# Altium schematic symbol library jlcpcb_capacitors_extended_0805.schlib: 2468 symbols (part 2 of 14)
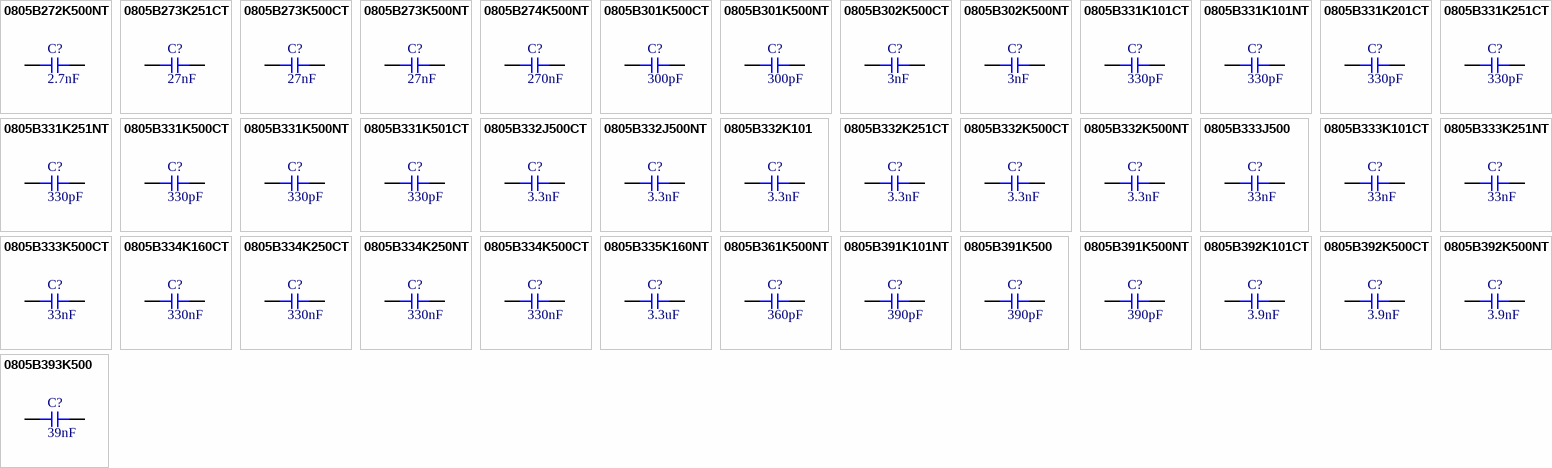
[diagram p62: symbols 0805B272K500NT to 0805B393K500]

## 0805B332K251CT
designator C?  Capacitance: 3.3nF  (hidden comment: *)
Capacitor, Ceramic (MLCC), 3.3nF, ±10%, 250V, X7R, ±10%, SMD 0805; Manufacturer: Walsin Tech Corp; Manufacturer Part Number: 0805B332K251CT
footprint CAP-0805 (0805 (2012M) Capacitor)
pins: 1, 2

## 0805B332K500CT
designator C?  Capacitance: 3.3nF  (hidden comment: *)
Capacitor, Ceramic (MLCC), 3.3nF, ±10%, 50V, X7R, ±10%, SMD 0805; Manufacturer: Walsin Tech Corp; Manufacturer Part Number: 0805B332K500CT
footprint CAP-0805 (0805 (2012M) Capacitor)
pins: 1, 2

## 0805B332K500NT
designator C?  Capacitance: 3.3nF  (hidden comment: *)
Capacitor, Ceramic (MLCC), 3.3nF, ±10%, 50V, X7R, ±10%, SMD 0805; Manufacturer: FH(Guangdong Fenghua Advanced Tech); Manufacturer Part Number: 0805B332K500NT
footprint CAP-0805 (0805 (2012M) Capacitor)
pins: 1, 2

## 0805B333J500
designator C?  Capacitance: 33nF  (hidden comment: *)
Capacitor, Ceramic (MLCC), 33nF, ±5%, 50V, X7R, ±5%, SMD 0805; Manufacturer: Walsin Tech Corp; Manufacturer Part Number: 0805B333J500
footprint CAP-0805 (0805 (2012M) Capacitor)
pins: 1, 2

## 0805B333K101CT
designator C?  Capacitance: 33nF  (hidden comment: *)
Capacitor, Ceramic (MLCC), 33nF, ±10%, 100V, X7R, ±10%, SMD 0805; Manufacturer: Walsin Tech Corp; Manufacturer Part Number: 0805B333K101CT
footprint CAP-0805 (0805 (2012M) Capacitor)
pins: 1, 2

## 0805B333K251NT
designator C?  Capacitance: 33nF  (hidden comment: *)
Capacitor, Ceramic (MLCC), 33nF, ±10%, 250V, ±10%, SMD 0805; Manufacturer: FH(Guangdong Fenghua Advanced Tech); Manufacturer Part Number: 0805B333K251NT
footprint CAP-0805 (0805 (2012M) Capacitor)
pins: 1, 2

## 0805B333K500CT
designator C?  Capacitance: 33nF  (hidden comment: *)
Capacitor, Ceramic (MLCC), 33nF, ±10%, 50V, X7R, ±10%, SMD 0805; Manufacturer: Walsin Tech Corp; Manufacturer Part Number: 0805B333K500CT
footprint CAP-0805 (0805 (2012M) Capacitor)
pins: 1, 2

## 0805B334K160CT
designator C?  Capacitance: 330nF  (hidden comment: *)
Capacitor, Ceramic (MLCC), 330nF, ±10%, 16V, X7R, ±10%, SMD 0805; Manufacturer: Walsin Tech Corp; Manufacturer Part Number: 0805B334K160CT
footprint CAP-0805 (0805 (2012M) Capacitor)
pins: 1, 2

## 0805B334K250CT
designator C?  Capacitance: 330nF  (hidden comment: *)
Capacitor, Ceramic (MLCC), 330nF, ±10%, 25V, X7R, ±10%, SMD 0805; Manufacturer: Walsin Tech Corp; Manufacturer Part Number: 0805B334K250CT
footprint CAP-0805 (0805 (2012M) Capacitor)
pins: 1, 2

## 0805B334K250NT
designator C?  Capacitance: 330nF  (hidden comment: *)
Capacitor, Ceramic (MLCC), 330nF, ±10%, 25V, X7R, ±10%, SMD 0805; Manufacturer: FH(Guangdong Fenghua Advanced Tech); Manufacturer Part Number: 0805B334K250NT
footprint CAP-0805 (0805 (2012M) Capacitor)
pins: 1, 2

## 0805B334K500CT
designator C?  Capacitance: 330nF  (hidden comment: *)
Capacitor, Ceramic (MLCC), 330nF, ±10%, 50V, X7R, ±10%, SMD 0805; Manufacturer: Walsin Tech Corp; Manufacturer Part Number: 0805B334K500CT
footprint CAP-0805 (0805 (2012M) Capacitor)
pins: 1, 2

## 0805B335K160NT
designator C?  Capacitance: 3.3uF  (hidden comment: *)
Capacitor, Ceramic (MLCC), 3.3uF, ±10%, 16V, X7R, ±10%, SMD 0805; Manufacturer: FH(Guangdong Fenghua Advanced Tech); Manufacturer Part Number: 0805B335K160NT
footprint CAP-0805 (0805 (2012M) Capacitor)
pins: 1, 2

## 0805B361K500NT
designator C?  Capacitance: 360pF  (hidden comment: *)
Capacitor, Ceramic (MLCC), 360pF, ±10%, 50V, X7R, ±10%, SMD 0805; Manufacturer: FH(Guangdong Fenghua Advanced Tech); Manufacturer Part Number: 0805B361K500NT
footprint CAP-0805 (0805 (2012M) Capacitor)
pins: 1, 2

## 0805B391K101NT
designator C?  Capacitance: 390pF  (hidden comment: *)
Capacitor, Ceramic (MLCC), 390pF, ±10%, 100V, X7R, ±10%, SMD 0805; Manufacturer: FH(Guangdong Fenghua Advanced Tech); Manufacturer Part Number: 0805B391K101NT
footprint CAP-0805 (0805 (2012M) Capacitor)
pins: 1, 2

## 0805B391K500
designator C?  Capacitance: 390pF  (hidden comment: *)
Capacitor, Ceramic (MLCC), 390pF, ±10%, 50V, X7R, ±10%, SMD 0805; Manufacturer: Walsin Tech Corp; Manufacturer Part Number: 0805B391K500
footprint CAP-0805 (0805 (2012M) Capacitor)
pins: 1, 2

## 0805B391K500NT
designator C?  Capacitance: 390pF  (hidden comment: *)
Capacitor, Ceramic (MLCC), 390pF, ±10%, 50V, X7R, ±10%, SMD 0805; Manufacturer: FH(Guangdong Fenghua Advanced Tech); Manufacturer Part Number: 0805B391K500NT
footprint CAP-0805 (0805 (2012M) Capacitor)
pins: 1, 2

## 0805B392K101CT
designator C?  Capacitance: 3.9nF  (hidden comment: *)
Capacitor, Ceramic (MLCC), 3.9nF, ±10%, 100V, X7R, ±10%, SMD 0805; Manufacturer: Walsin Tech Corp; Manufacturer Part Number: 0805B392K101CT
footprint CAP-0805 (0805 (2012M) Capacitor)
pins: 1, 2

## 0805B392K500CT
designator C?  Capacitance: 3.9nF  (hidden comment: *)
Capacitor, Ceramic (MLCC), 3.9nF, ±10%, 50V, X7R, ±10%, SMD 0805; Manufacturer: Walsin Tech Corp; Manufacturer Part Number: 0805B392K500CT
footprint CAP-0805 (0805 (2012M) Capacitor)
pins: 1, 2

## 0805B392K500NT
designator C?  Capacitance: 3.9nF  (hidden comment: *)
Capacitor, Ceramic (MLCC), 3.9nF, ±10%, 50V, X7R, ±10%, SMD 0805; Manufacturer: FH(Guangdong Fenghua Advanced Tech); Manufacturer Part Number: 0805B392K500NT
footprint CAP-0805 (0805 (2012M) Capacitor)
pins: 1, 2

## 0805B393K500
designator C?  Capacitance: 39nF  (hidden comment: *)
Capacitor, Ceramic (MLCC), 39nF, ±10%, 50V, X7R, ±10%, SMD 0805; Manufacturer: Walsin Tech Corp; Manufacturer Part Number: 0805B393K500
footprint CAP-0805 (0805 (2012M) Capacitor)
pins: 1, 2

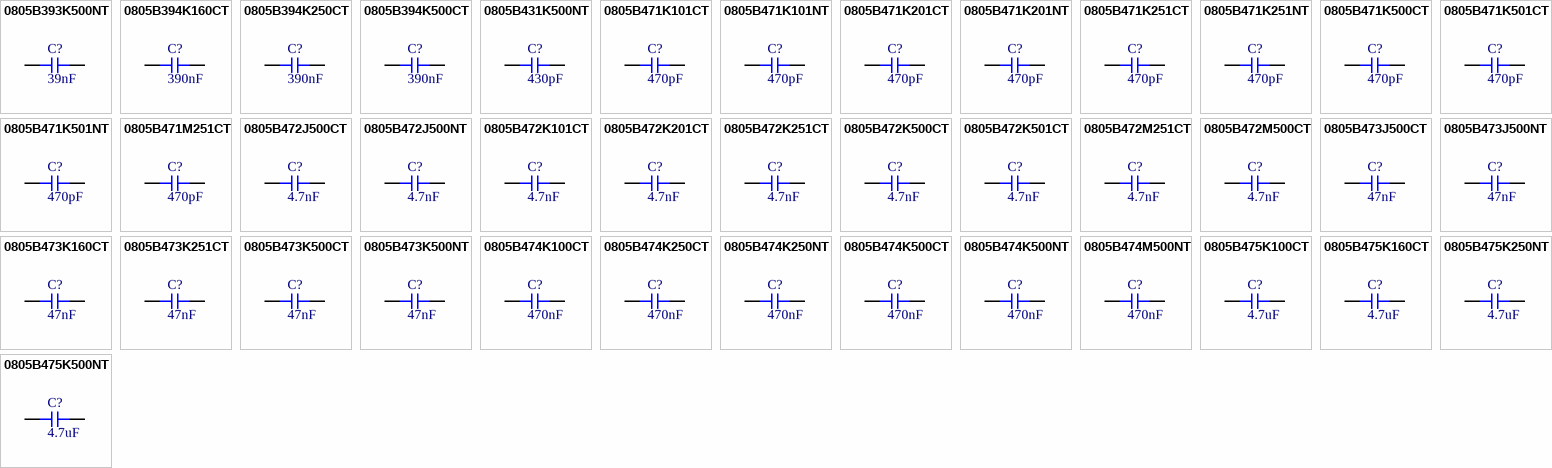
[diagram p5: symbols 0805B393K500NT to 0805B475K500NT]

## 0805B393K500NT
designator C?  Capacitance: 39nF  (hidden comment: *)
Capacitor, Ceramic (MLCC), 39nF, ±10%, 50V, X7R, ±10%, SMD 0805; Manufacturer: FH(Guangdong Fenghua Advanced Tech); Manufacturer Part Number: 0805B393K500NT
footprint CAP-0805 (0805 (2012M) Capacitor)
pins: 1, 2

## 0805B394K160CT
designator C?  Capacitance: 390nF  (hidden comment: *)
Capacitor, Ceramic (MLCC), 390nF, ±10%, 16V, X7R, ±10%, SMD 0805; Manufacturer: Walsin Tech Corp; Manufacturer Part Number: 0805B394K160CT
footprint CAP-0805 (0805 (2012M) Capacitor)
pins: 1, 2

## 0805B394K250CT
designator C?  Capacitance: 390nF  (hidden comment: *)
Capacitor, Ceramic (MLCC), 390nF, ±10%, 25V, X7R, ±10%, SMD 0805; Manufacturer: Walsin Tech Corp; Manufacturer Part Number: 0805B394K250CT
footprint CAP-0805 (0805 (2012M) Capacitor)
pins: 1, 2

## 0805B394K500CT
designator C?  Capacitance: 390nF  (hidden comment: *)
Capacitor, Ceramic (MLCC), 390nF, ±10%, 50V, X7R, ±10%, SMD 0805; Manufacturer: Walsin Tech Corp; Manufacturer Part Number: 0805B394K500CT
footprint CAP-0805 (0805 (2012M) Capacitor)
pins: 1, 2

## 0805B431K500NT
designator C?  Capacitance: 430pF  (hidden comment: *)
Capacitor, Ceramic (MLCC), 430pF, ±10%, 50V, X7R, ±10%, SMD 0805; Manufacturer: FH(Guangdong Fenghua Advanced Tech); Manufacturer Part Number: 0805B431K500NT
footprint CAP-0805 (0805 (2012M) Capacitor)
pins: 1, 2

## 0805B471K101CT
designator C?  Capacitance: 470pF  (hidden comment: *)
Capacitor, Ceramic (MLCC), 470pF, ±10%, 100V, X7R, ±10%, SMD 0805; Manufacturer: Walsin Tech Corp; Manufacturer Part Number: 0805B471K101CT
footprint CAP-0805 (0805 (2012M) Capacitor)
pins: 1, 2

## 0805B471K101NT
designator C?  Capacitance: 470pF  (hidden comment: *)
Capacitor, Ceramic (MLCC), 470pF, ±10%, 100V, X7R, ±10%, SMD 0805; Manufacturer: FH(Guangdong Fenghua Advanced Tech); Manufacturer Part Number: 0805B471K101NT
footprint CAP-0805 (0805 (2012M) Capacitor)
pins: 1, 2

## 0805B471K201CT
designator C?  Capacitance: 470pF  (hidden comment: *)
Capacitor, Ceramic (MLCC), 470pF, ±10%, 200V, X7R, ±10%, SMD 0805; Manufacturer: Walsin Tech Corp; Manufacturer Part Number: 0805B471K201CT
footprint CAP-0805 (0805 (2012M) Capacitor)
pins: 1, 2

## 0805B471K201NT
designator C?  Capacitance: 470pF  (hidden comment: *)
Capacitor, Ceramic (MLCC), 470pF, ±10%, 200V, X7R, ±10%, SMD 0805; Manufacturer: FH(Guangdong Fenghua Advanced Tech); Manufacturer Part Number: 0805B471K201NT
footprint CAP-0805 (0805 (2012M) Capacitor)
pins: 1, 2

## 0805B471K251CT
designator C?  Capacitance: 470pF  (hidden comment: *)
Capacitor, Ceramic (MLCC), 470pF, ±10%, 250V, X7R, ±10%, SMD 0805; Manufacturer: Walsin Tech Corp; Manufacturer Part Number: 0805B471K251CT
footprint CAP-0805 (0805 (2012M) Capacitor)
pins: 1, 2

## 0805B471K251NT
designator C?  Capacitance: 470pF  (hidden comment: *)
Capacitor, Ceramic (MLCC), 470pF, ±10%, 250V, X7R, ±10%, SMD 0805; Manufacturer: FH(Guangdong Fenghua Advanced Tech); Manufacturer Part Number: 0805B471K251NT
footprint CAP-0805 (0805 (2012M) Capacitor)
pins: 1, 2

## 0805B471K500CT
designator C?  Capacitance: 470pF  (hidden comment: *)
Capacitor, Ceramic (MLCC), 470pF, ±10%, 50V, X7R, ±10%, SMD 0805; Manufacturer: Walsin Tech Corp; Manufacturer Part Number: 0805B471K500CT
footprint CAP-0805 (0805 (2012M) Capacitor)
pins: 1, 2

## 0805B471K501CT
designator C?  Capacitance: 470pF  (hidden comment: *)
Capacitor, Ceramic (MLCC), 470pF, ±10%, 500V, X7R, ±10%, SMD 0805; Manufacturer: Walsin Tech Corp; Manufacturer Part Number: 0805B471K501CT
footprint CAP-0805 (0805 (2012M) Capacitor)
pins: 1, 2

## 0805B471K501NT
designator C?  Capacitance: 470pF  (hidden comment: *)
Capacitor, Ceramic (MLCC), 470pF, ±10%, 500V, ±10%, SMD 0805; Manufacturer: FH(Guangdong Fenghua Advanced Tech); Manufacturer Part Number: 0805B471K501NT
footprint CAP-0805 (0805 (2012M) Capacitor)
pins: 1, 2

## 0805B471M251CT
designator C?  Capacitance: 470pF  (hidden comment: *)
Capacitor, Ceramic (MLCC), 470pF, ±20%, 250V, X7R, ±20%, SMD 0805; Manufacturer: Walsin Tech Corp; Manufacturer Part Number: 0805B471M251CT
footprint CAP-0805 (0805 (2012M) Capacitor)
pins: 1, 2

## 0805B472J500CT
designator C?  Capacitance: 4.7nF  (hidden comment: *)
Capacitor, Ceramic (MLCC), 4.7nF, ±5%, 50V, X7R, ±5%, SMD 0805; Manufacturer: Walsin Tech Corp; Manufacturer Part Number: 0805B472J500CT
footprint CAP-0805 (0805 (2012M) Capacitor)
pins: 1, 2

## 0805B472J500NT
designator C?  Capacitance: 4.7nF  (hidden comment: *)
Capacitor, Ceramic (MLCC), 4.7nF, ±5%, 50V, X7R, ±5%, SMD 0805; Manufacturer: FH (Guangdong Fenghua Advanced Tech); Manufacturer Part Number: 0805B472J500NT
footprint CAP-0805 (0805 (2012M) Capacitor)
pins: 1, 2

## 0805B472K101CT
designator C?  Capacitance: 4.7nF  (hidden comment: *)
Capacitor, Ceramic (MLCC), 4.7nF, ±10%, 100V, X7R, ±10%, SMD 0805; Manufacturer: Walsin Tech Corp; Manufacturer Part Number: 0805B472K101CT
footprint CAP-0805 (0805 (2012M) Capacitor)
pins: 1, 2

## 0805B472K201CT
designator C?  Capacitance: 4.7nF  (hidden comment: *)
Capacitor, Ceramic (MLCC), 4.7nF, ±10%, 200V, X7R, ±10%, SMD 0805; Manufacturer: Walsin Tech Corp; Manufacturer Part Number: 0805B472K201CT
footprint CAP-0805 (0805 (2012M) Capacitor)
pins: 1, 2

## 0805B472K251CT
designator C?  Capacitance: 4.7nF  (hidden comment: *)
Capacitor, Ceramic (MLCC), 4.7nF, ±10%, 250V, X7R, ±10%, SMD 0805; Manufacturer: Walsin Tech Corp; Manufacturer Part Number: 0805B472K251CT
footprint CAP-0805 (0805 (2012M) Capacitor)
pins: 1, 2

## 0805B472K500CT
designator C?  Capacitance: 4.7nF  (hidden comment: *)
Capacitor, Ceramic (MLCC), 4.7nF, ±10%, 50V, X7R, ±10%, SMD 0805; Manufacturer: Walsin Tech Corp; Manufacturer Part Number: 0805B472K500CT
footprint CAP-0805 (0805 (2012M) Capacitor)
pins: 1, 2

## 0805B472K501CT
designator C?  Capacitance: 4.7nF  (hidden comment: *)
Capacitor, Ceramic (MLCC), 4.7nF, ±10%, 500V, X7R, ±10%, SMD 0805; Manufacturer: Walsin Tech Corp; Manufacturer Part Number: 0805B472K501CT
footprint CAP-0805 (0805 (2012M) Capacitor)
pins: 1, 2

## 0805B472M251CT
designator C?  Capacitance: 4.7nF  (hidden comment: *)
Capacitor, Ceramic (MLCC), 4.7nF, ±20%, 250V, X7R, ±20%, SMD 0805; Manufacturer: Walsin Tech Corp; Manufacturer Part Number: 0805B472M251CT
footprint CAP-0805 (0805 (2012M) Capacitor)
pins: 1, 2

## 0805B472M500CT
designator C?  Capacitance: 4.7nF  (hidden comment: *)
Capacitor, Ceramic (MLCC), 4.7nF, ±20%, 50V, X7R, ±20%, SMD 0805; Manufacturer: Walsin Tech Corp; Manufacturer Part Number: 0805B472M500CT
footprint CAP-0805 (0805 (2012M) Capacitor)
pins: 1, 2

## 0805B473J500CT
designator C?  Capacitance: 47nF  (hidden comment: *)
Capacitor, Ceramic (MLCC), 47nF, ±5%, 50V, X7R, ±5%, SMD 0805; Manufacturer: Walsin Tech Corp; Manufacturer Part Number: 0805B473J500CT
footprint CAP-0805 (0805 (2012M) Capacitor)
pins: 1, 2

## 0805B473J500NT
designator C?  Capacitance: 47nF  (hidden comment: *)
Capacitor, Ceramic (MLCC), 47nF, ±5%, 50V, X7R, ±5%, SMD 0805; Manufacturer: FH(Guangdong Fenghua Advanced Tech); Manufacturer Part Number: 0805B473J500NT
footprint CAP-0805 (0805 (2012M) Capacitor)
pins: 1, 2

## 0805B473K160CT
designator C?  Capacitance: 47nF  (hidden comment: *)
Capacitor, Ceramic (MLCC), 47nF, ±10%, 16V, X7R, ±10%, SMD 0805; Manufacturer: Walsin Tech Corp; Manufacturer Part Number: 0805B473K160CT
footprint CAP-0805 (0805 (2012M) Capacitor)
pins: 1, 2

## 0805B473K251CT
designator C?  Capacitance: 47nF  (hidden comment: *)
Capacitor, Ceramic (MLCC), 47nF, ±10%, 250V, X7R, ±10%, SMD 0805; Manufacturer: Walsin Tech Corp; Manufacturer Part Number: 0805B473K251CT
footprint CAP-0805 (0805 (2012M) Capacitor)
pins: 1, 2

## 0805B473K500CT
designator C?  Capacitance: 47nF  (hidden comment: *)
Capacitor, Ceramic (MLCC), 47nF, ±10%, 50V, X7R, ±10%, SMD 0805; Manufacturer: Walsin Tech Corp; Manufacturer Part Number: 0805B473K500CT
footprint CAP-0805 (0805 (2012M) Capacitor)
pins: 1, 2

## 0805B473K500NT
designator C?  Capacitance: 47nF  (hidden comment: *)
Capacitor, Ceramic (MLCC), 47nF, ±10%, 50V, X7R, ±10%, SMD 0805; Manufacturer: FH(Guangdong Fenghua Advanced Tech); Manufacturer Part Number: 0805B473K500NT
footprint CAP-0805 (0805 (2012M) Capacitor)
pins: 1, 2

## 0805B474K100CT
designator C?  Capacitance: 470nF  (hidden comment: *)
Capacitor, Ceramic (MLCC), 470nF, ±10%, 10V, X7R, ±10%, SMD 0805; Manufacturer: Walsin Tech Corp; Manufacturer Part Number: 0805B474K100CT
footprint CAP-0805 (0805 (2012M) Capacitor)
pins: 1, 2

## 0805B474K250CT
designator C?  Capacitance: 470nF  (hidden comment: *)
Capacitor, Ceramic (MLCC), 470nF, ±10%, 25V, X7R, ±10%, SMD 0805; Manufacturer: Walsin Tech Corp; Manufacturer Part Number: 0805B474K250CT
footprint CAP-0805 (0805 (2012M) Capacitor)
pins: 1, 2

## 0805B474K250NT
designator C?  Capacitance: 470nF  (hidden comment: *)
Capacitor, Ceramic (MLCC), 470nF, ±10%, 25V, X7R, ±10%, SMD 0805; Manufacturer: FH(Guangdong Fenghua Advanced Tech); Manufacturer Part Number: 0805B474K250NT
footprint CAP-0805 (0805 (2012M) Capacitor)
pins: 1, 2

## 0805B474K500CT
designator C?  Capacitance: 470nF  (hidden comment: *)
Capacitor, Ceramic (MLCC), 470nF, ±10%, 50V, X7R, ±10%, SMD 0805; Manufacturer: Walsin Tech Corp; Manufacturer Part Number: 0805B474K500CT
footprint CAP-0805 (0805 (2012M) Capacitor)
pins: 1, 2

## 0805B474K500NT
designator C?  Capacitance: 470nF  (hidden comment: *)
Capacitor, Ceramic (MLCC), 470nF, ±10%, 50V, X7R, ±10%, SMD 0805; Manufacturer: FH(Guangdong Fenghua Advanced Tech); Manufacturer Part Number: 0805B474K500NT
footprint CAP-0805 (0805 (2012M) Capacitor)
pins: 1, 2

## 0805B474M500NT
designator C?  Capacitance: 470nF  (hidden comment: *)
Capacitor, Ceramic (MLCC), 470nF, ±20%, 50V, ±20%, SMD 0805; Manufacturer: FH (Guangdong Fenghua Advanced Tech); Manufacturer Part Number: 0805B474M500NT
footprint CAP-0805 (0805 (2012M) Capacitor)
pins: 1, 2

## 0805B475K100CT
designator C?  Capacitance: 4.7uF  (hidden comment: *)
Capacitor, Ceramic (MLCC), 4.7uF, ±10%, 10V, X7R, ±10%, SMD 0805; Manufacturer: Walsin Tech Corp; Manufacturer Part Number: 0805B475K100CT
footprint CAP-0805 (0805 (2012M) Capacitor)
pins: 1, 2

## 0805B475K160CT
designator C?  Capacitance: 4.7uF  (hidden comment: *)
Capacitor, Ceramic (MLCC), 4.7uF, ±10%, 16V, X7R, ±10%, SMD 0805; Manufacturer: Walsin Tech Corp; Manufacturer Part Number: 0805B475K160CT
footprint CAP-0805 (0805 (2012M) Capacitor)
pins: 1, 2

## 0805B475K250NT
designator C?  Capacitance: 4.7uF  (hidden comment: *)
Capacitor, Ceramic (MLCC), 4.7uF, ±10%, 25V, ±10%, SMD 0805; Manufacturer: FH (Guangdong Fenghua Advanced Tech); Manufacturer Part Number: 0805B475K250NT
footprint CAP-0805 (0805 (2012M) Capacitor)
pins: 1, 2

## 0805B475K500NT
designator C?  Capacitance: 4.7uF  (hidden comment: *)
Capacitor, Ceramic (MLCC), 4.7uF, ±10%, 50V, X7R, ±10%, SMD 0805; Manufacturer: FH (Guangdong Fenghua Advanced Tech); Manufacturer Part Number: 0805B475K500NT
footprint CAP-0805 (0805 (2012M) Capacitor)
pins: 1, 2

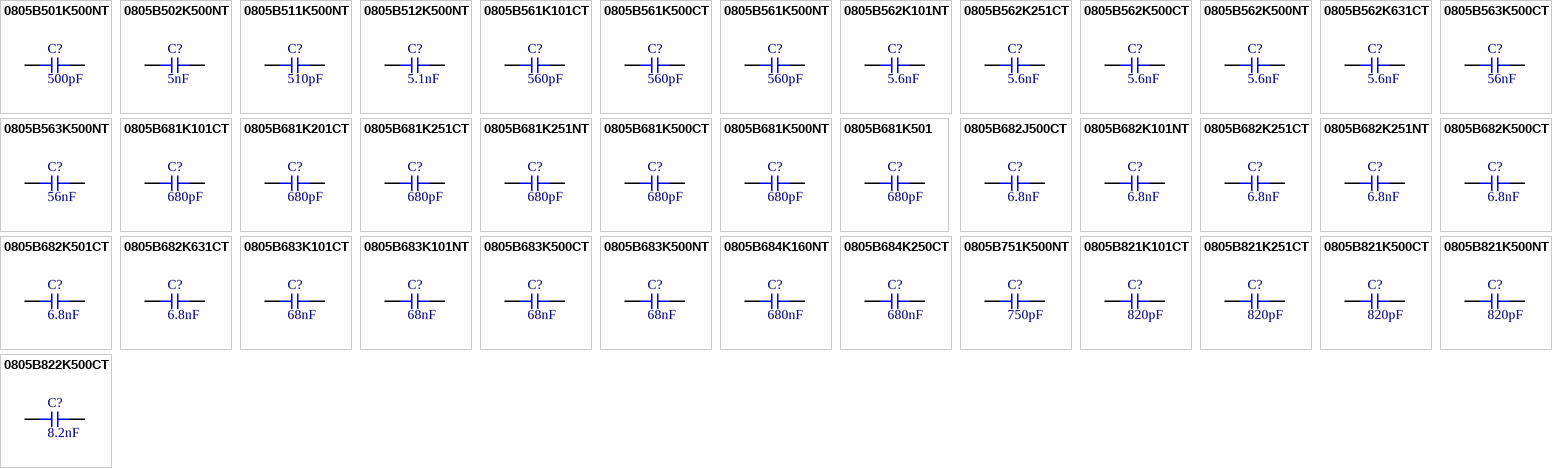
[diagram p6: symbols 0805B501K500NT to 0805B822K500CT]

## 0805B501K500NT
designator C?  Capacitance: 500pF  (hidden comment: *)
Capacitor, Ceramic (MLCC), 500pF, ±10%, 50V, X7R, ±10%, SMD 0805; Manufacturer: FH(Guangdong Fenghua Advanced Tech); Manufacturer Part Number: 0805B501K500NT
footprint CAP-0805 (0805 (2012M) Capacitor)
pins: 1, 2

## 0805B502K500NT
designator C?  Capacitance: 5nF  (hidden comment: *)
Capacitor, Ceramic (MLCC), 5nF, ±10%, 50V, X7R, ±10%, SMD 0805; Manufacturer: FH(Guangdong Fenghua Advanced Tech); Manufacturer Part Number: 0805B502K500NT
footprint CAP-0805 (0805 (2012M) Capacitor)
pins: 1, 2

## 0805B511K500NT
designator C?  Capacitance: 510pF  (hidden comment: *)
Capacitor, Ceramic (MLCC), 510pF, ±10%, 50V, X7R, ±10%, SMD 0805; Manufacturer: FH(Guangdong Fenghua Advanced Tech); Manufacturer Part Number: 0805B511K500NT
footprint CAP-0805 (0805 (2012M) Capacitor)
pins: 1, 2

## 0805B512K500NT
designator C?  Capacitance: 5.1nF  (hidden comment: *)
Capacitor, Ceramic (MLCC), 5.1nF, ±10%, 50V, X7R, ±10%, SMD 0805; Manufacturer: FH(Guangdong Fenghua Advanced Tech); Manufacturer Part Number: 0805B512K500NT
footprint CAP-0805 (0805 (2012M) Capacitor)
pins: 1, 2

## 0805B561K101CT
designator C?  Capacitance: 560pF  (hidden comment: *)
Capacitor, Ceramic (MLCC), 560pF, ±10%, 100V, X7R, ±10%, SMD 0805; Manufacturer: Walsin Tech Corp; Manufacturer Part Number: 0805B561K101CT
footprint CAP-0805 (0805 (2012M) Capacitor)
pins: 1, 2

## 0805B561K500CT
designator C?  Capacitance: 560pF  (hidden comment: *)
Capacitor, Ceramic (MLCC), 560pF, ±10%, 50V, X7R, ±10%, SMD 0805; Manufacturer: Walsin Tech Corp; Manufacturer Part Number: 0805B561K500CT
footprint CAP-0805 (0805 (2012M) Capacitor)
pins: 1, 2

## 0805B561K500NT
designator C?  Capacitance: 560pF  (hidden comment: *)
Capacitor, Ceramic (MLCC), 560pF, ±10%, 50V, X7R, ±10%, SMD 0805; Manufacturer: FH(Guangdong Fenghua Advanced Tech); Manufacturer Part Number: 0805B561K500NT
footprint CAP-0805 (0805 (2012M) Capacitor)
pins: 1, 2

## 0805B562K101NT
designator C?  Capacitance: 5.6nF  (hidden comment: *)
Capacitor, Ceramic (MLCC), 5.6nF, ±10%, 100V, X7R, ±10%, SMD 0805; Manufacturer: FH(Guangdong Fenghua Advanced Tech); Manufacturer Part Number: 0805B562K101NT
footprint CAP-0805 (0805 (2012M) Capacitor)
pins: 1, 2

## 0805B562K251CT
designator C?  Capacitance: 5.6nF  (hidden comment: *)
Capacitor, Ceramic (MLCC), 5.6nF, ±10%, 250V, X7R, ±10%, SMD 0805; Manufacturer: Walsin Tech Corp; Manufacturer Part Number: 0805B562K251CT
footprint CAP-0805 (0805 (2012M) Capacitor)
pins: 1, 2

## 0805B562K500CT
designator C?  Capacitance: 5.6nF  (hidden comment: *)
Capacitor, Ceramic (MLCC), 5.6nF, ±10%, 50V, X7R, ±10%, SMD 0805; Manufacturer: Walsin Tech Corp; Manufacturer Part Number: 0805B562K500CT
footprint CAP-0805 (0805 (2012M) Capacitor)
pins: 1, 2

## 0805B562K500NT
designator C?  Capacitance: 5.6nF  (hidden comment: *)
Capacitor, Ceramic (MLCC), 5.6nF, ±10%, 50V, X7R, ±10%, SMD 0805; Manufacturer: FH(Guangdong Fenghua Advanced Tech); Manufacturer Part Number: 0805B562K500NT
footprint CAP-0805 (0805 (2012M) Capacitor)
pins: 1, 2

## 0805B562K631CT
designator C?  Capacitance: 5.6nF  (hidden comment: *)
Capacitor, Ceramic (MLCC), 5.6nF, ±10%, 630V, X7R, ±10%, SMD 0805; Manufacturer: Walsin Tech Corp; Manufacturer Part Number: 0805B562K631CT
footprint CAP-0805 (0805 (2012M) Capacitor)
pins: 1, 2

## 0805B563K500CT
designator C?  Capacitance: 56nF  (hidden comment: *)
Capacitor, Ceramic (MLCC), 56nF, ±10%, 50V, X7R, ±10%, SMD 0805; Manufacturer: Walsin Tech Corp; Manufacturer Part Number: 0805B563K500CT
footprint CAP-0805 (0805 (2012M) Capacitor)
pins: 1, 2

## 0805B563K500NT
designator C?  Capacitance: 56nF  (hidden comment: *)
Capacitor, Ceramic (MLCC), 56nF, ±10%, 50V, X7R, ±10%, SMD 0805; Manufacturer: FH(Guangdong Fenghua Advanced Tech); Manufacturer Part Number: 0805B563K500NT
footprint CAP-0805 (0805 (2012M) Capacitor)
pins: 1, 2

## 0805B681K101CT
designator C?  Capacitance: 680pF  (hidden comment: *)
Capacitor, Ceramic (MLCC), 680pF, ±10%, 100V, X7R, ±10%, SMD 0805; Manufacturer: Walsin Tech Corp; Manufacturer Part Number: 0805B681K101CT
footprint CAP-0805 (0805 (2012M) Capacitor)
pins: 1, 2

## 0805B681K201CT
designator C?  Capacitance: 680pF  (hidden comment: *)
Capacitor, Ceramic (MLCC), 680pF, ±10%, 200V, X7R, ±10%, SMD 0805; Manufacturer: Walsin Tech Corp; Manufacturer Part Number: 0805B681K201CT
footprint CAP-0805 (0805 (2012M) Capacitor)
pins: 1, 2

## 0805B681K251CT
designator C?  Capacitance: 680pF  (hidden comment: *)
Capacitor, Ceramic (MLCC), 680pF, ±10%, 250V, X7R, ±10%, SMD 0805; Manufacturer: Walsin Tech Corp; Manufacturer Part Number: 0805B681K251CT
footprint CAP-0805 (0805 (2012M) Capacitor)
pins: 1, 2

## 0805B681K251NT
designator C?  Capacitance: 680pF  (hidden comment: *)
Capacitor, Ceramic (MLCC), 680pF, ±10%, 250V, ±10%, SMD 0805; Manufacturer: FH(Guangdong Fenghua Advanced Tech); Manufacturer Part Number: 0805B681K251NT
footprint CAP-0805 (0805 (2012M) Capacitor)
pins: 1, 2

## 0805B681K500CT
designator C?  Capacitance: 680pF  (hidden comment: *)
Capacitor, Ceramic (MLCC), 680pF, ±10%, 50V, X7R, ±10%, SMD 0805; Manufacturer: Walsin Tech Corp; Manufacturer Part Number: 0805B681K500CT
footprint CAP-0805 (0805 (2012M) Capacitor)
pins: 1, 2

## 0805B681K500NT
designator C?  Capacitance: 680pF  (hidden comment: *)
Capacitor, Ceramic (MLCC), 680pF, ±10%, 50V, X7R, ±10%, SMD 0805; Manufacturer: FH(Guangdong Fenghua Advanced Tech); Manufacturer Part Number: 0805B681K500NT
footprint CAP-0805 (0805 (2012M) Capacitor)
pins: 1, 2

## 0805B681K501
designator C?  Capacitance: 680pF  (hidden comment: *)
Capacitor, Ceramic (MLCC), 680pF, ±10%, 500V, X7R, ±10%, SMD 0805; Manufacturer: Walsin Tech Corp; Manufacturer Part Number: 0805B681K501
footprint CAP-0805 (0805 (2012M) Capacitor)
pins: 1, 2

## 0805B682J500CT
designator C?  Capacitance: 6.8nF  (hidden comment: *)
Capacitor, Ceramic (MLCC), 6.8nF, ±5%, 50V, X7R, ±5%, SMD 0805; Manufacturer: Walsin Tech Corp; Manufacturer Part Number: 0805B682J500CT
footprint CAP-0805 (0805 (2012M) Capacitor)
pins: 1, 2

## 0805B682K101NT
designator C?  Capacitance: 6.8nF  (hidden comment: *)
Capacitor, Ceramic (MLCC), 6.8nF, ±10%, 100V, X7R, ±10%, SMD 0805; Manufacturer: FH(Guangdong Fenghua Advanced Tech); Manufacturer Part Number: 0805B682K101NT
footprint CAP-0805 (0805 (2012M) Capacitor)
pins: 1, 2

## 0805B682K251CT
designator C?  Capacitance: 6.8nF  (hidden comment: *)
Capacitor, Ceramic (MLCC), 6.8nF, ±10%, 250V, X7R, ±10%, SMD 0805; Manufacturer: Walsin Tech Corp; Manufacturer Part Number: 0805B682K251CT
footprint CAP-0805 (0805 (2012M) Capacitor)
pins: 1, 2

## 0805B682K251NT
designator C?  Capacitance: 6.8nF  (hidden comment: *)
Capacitor, Ceramic (MLCC), 6.8nF, ±10%, 250V, ±10%, SMD 0805; Manufacturer: FH(Guangdong Fenghua Advanced Tech); Manufacturer Part Number: 0805B682K251NT
footprint CAP-0805 (0805 (2012M) Capacitor)
pins: 1, 2

## 0805B682K500CT
designator C?  Capacitance: 6.8nF  (hidden comment: *)
Capacitor, Ceramic (MLCC), 6.8nF, ±10%, 50V, X7R, ±10%, SMD 0805; Manufacturer: Walsin Tech Corp; Manufacturer Part Number: 0805B682K500CT
footprint CAP-0805 (0805 (2012M) Capacitor)
pins: 1, 2

## 0805B682K501CT
designator C?  Capacitance: 6.8nF  (hidden comment: *)
Capacitor, Ceramic (MLCC), 6.8nF, ±10%, 500V, X7R, ±10%, SMD 0805; Manufacturer: Walsin Tech Corp; Manufacturer Part Number: 0805B682K501CT
footprint CAP-0805 (0805 (2012M) Capacitor)
pins: 1, 2

## 0805B682K631CT
designator C?  Capacitance: 6.8nF  (hidden comment: *)
Capacitor, Ceramic (MLCC), 6.8nF, ±10%, 630V, X7R, ±10%, SMD 0805; Manufacturer: Walsin Tech Corp; Manufacturer Part Number: 0805B682K631CT
footprint CAP-0805 (0805 (2012M) Capacitor)
pins: 1, 2

## 0805B683K101CT
designator C?  Capacitance: 68nF  (hidden comment: *)
Capacitor, Ceramic (MLCC), 68nF, ±10%, 100V, X7R, ±10%, SMD 0805; Manufacturer: Walsin Tech Corp; Manufacturer Part Number: 0805B683K101CT
footprint CAP-0805 (0805 (2012M) Capacitor)
pins: 1, 2

## 0805B683K101NT
designator C?  Capacitance: 68nF  (hidden comment: *)
Capacitor, Ceramic (MLCC), 68nF, ±10%, 100V, X7R, ±10%, SMD 0805; Manufacturer: FH(Guangdong Fenghua Advanced Tech); Manufacturer Part Number: 0805B683K101NT
footprint CAP-0805 (0805 (2012M) Capacitor)
pins: 1, 2

## 0805B683K500CT
designator C?  Capacitance: 68nF  (hidden comment: *)
Capacitor, Ceramic (MLCC), 68nF, ±10%, 50V, X7R, ±10%, SMD 0805; Manufacturer: Walsin Tech Corp; Manufacturer Part Number: 0805B683K500CT
footprint CAP-0805 (0805 (2012M) Capacitor)
pins: 1, 2

## 0805B683K500NT
designator C?  Capacitance: 68nF  (hidden comment: *)
Capacitor, Ceramic (MLCC), 68nF, ±10%, 50V, X7R, ±10%, SMD 0805; Manufacturer: FH(Guangdong Fenghua Advanced Tech); Manufacturer Part Number: 0805B683K500NT
footprint CAP-0805 (0805 (2012M) Capacitor)
pins: 1, 2

## 0805B684K160NT
designator C?  Capacitance: 680nF  (hidden comment: *)
Capacitor, Ceramic (MLCC), 680nF, ±10%, 16V, X7R, ±10%, SMD 0805; Manufacturer: FH(Guangdong Fenghua Advanced Tech); Manufacturer Part Number: 0805B684K160NT
footprint CAP-0805 (0805 (2012M) Capacitor)
pins: 1, 2

## 0805B684K250CT
designator C?  Capacitance: 680nF  (hidden comment: *)
Capacitor, Ceramic (MLCC), 680nF, ±10%, 25V, X7R, ±10%, SMD 0805; Manufacturer: Walsin Tech Corp; Manufacturer Part Number: 0805B684K250CT
footprint CAP-0805 (0805 (2012M) Capacitor)
pins: 1, 2

## 0805B751K500NT
designator C?  Capacitance: 750pF  (hidden comment: *)
Capacitor, Ceramic (MLCC), 750pF, ±10%, 50V, X7R, ±10%, SMD 0805; Manufacturer: FH(Guangdong Fenghua Advanced Tech); Manufacturer Part Number: 0805B751K500NT
footprint CAP-0805 (0805 (2012M) Capacitor)
pins: 1, 2

## 0805B821K101CT
designator C?  Capacitance: 820pF  (hidden comment: *)
Capacitor, Ceramic (MLCC), 820pF, ±10%, 100V, X7R, ±10%, SMD 0805; Manufacturer: Walsin Tech Corp; Manufacturer Part Number: 0805B821K101CT
footprint CAP-0805 (0805 (2012M) Capacitor)
pins: 1, 2

## 0805B821K251CT
designator C?  Capacitance: 820pF  (hidden comment: *)
Capacitor, Ceramic (MLCC), 820pF, ±10%, 250V, X7R, ±10%, SMD 0805; Manufacturer: Walsin Tech Corp; Manufacturer Part Number: 0805B821K251CT
footprint CAP-0805 (0805 (2012M) Capacitor)
pins: 1, 2

## 0805B821K500CT
designator C?  Capacitance: 820pF  (hidden comment: *)
Capacitor, Ceramic (MLCC), 820pF, ±10%, 50V, X7R, ±10%, SMD 0805; Manufacturer: Walsin Tech Corp; Manufacturer Part Number: 0805B821K500CT
footprint CAP-0805 (0805 (2012M) Capacitor)
pins: 1, 2

## 0805B821K500NT
designator C?  Capacitance: 820pF  (hidden comment: *)
Capacitor, Ceramic (MLCC), 820pF, ±10%, 50V, X7R, ±10%, SMD 0805; Manufacturer: FH(Guangdong Fenghua Advanced Tech); Manufacturer Part Number: 0805B821K500NT
footprint CAP-0805 (0805 (2012M) Capacitor)
pins: 1, 2

## 0805B822K500CT
designator C?  Capacitance: 8.2nF  (hidden comment: *)
Capacitor, Ceramic (MLCC), 8.2nF, ±10%, 50V, X7R, ±10%, SMD 0805; Manufacturer: Walsin Tech Corp; Manufacturer Part Number: 0805B822K500CT
footprint CAP-0805 (0805 (2012M) Capacitor)
pins: 1, 2

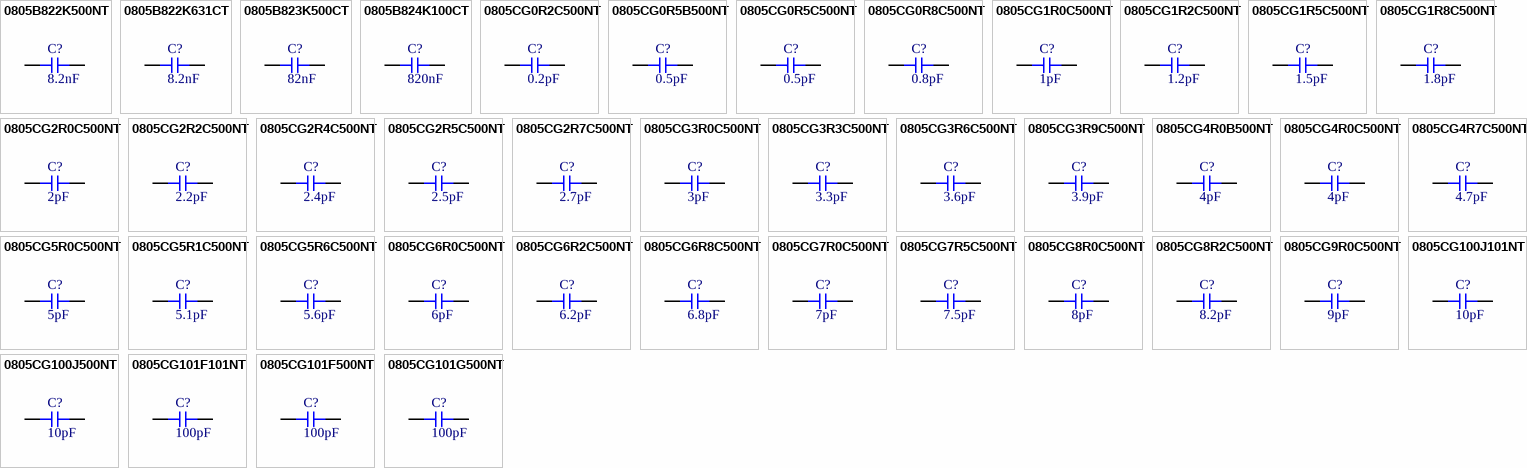
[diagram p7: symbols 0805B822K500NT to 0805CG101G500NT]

## 0805B822K500NT
designator C?  Capacitance: 8.2nF  (hidden comment: *)
Capacitor, Ceramic (MLCC), 8.2nF, ±10%, 50V, X7R, ±10%, SMD 0805; Manufacturer: FH(Guangdong Fenghua Advanced Tech); Manufacturer Part Number: 0805B822K500NT
footprint CAP-0805 (0805 (2012M) Capacitor)
pins: 1, 2

## 0805B822K631CT
designator C?  Capacitance: 8.2nF  (hidden comment: *)
Capacitor, Ceramic (MLCC), 8.2nF, ±10%, 630V, X7R, ±10%, SMD 0805; Manufacturer: Walsin Tech Corp; Manufacturer Part Number: 0805B822K631CT
footprint CAP-0805 (0805 (2012M) Capacitor)
pins: 1, 2

## 0805B823K500CT
designator C?  Capacitance: 82nF  (hidden comment: *)
Capacitor, Ceramic (MLCC), 82nF, ±10%, 50V, X7R, ±10%, SMD 0805; Manufacturer: Walsin Tech Corp; Manufacturer Part Number: 0805B823K500CT
footprint CAP-0805 (0805 (2012M) Capacitor)
pins: 1, 2

## 0805B824K100CT
designator C?  Capacitance: 820nF  (hidden comment: *)
Capacitor, Ceramic (MLCC), 820nF, ±10%, 10V, X7R, ±10%, SMD 0805; Manufacturer: Walsin Tech Corp; Manufacturer Part Number: 0805B824K100CT
footprint CAP-0805 (0805 (2012M) Capacitor)
pins: 1, 2

## 0805CG0R2C500NT
designator C?  Capacitance: 0.2pF  (hidden comment: *)
Capacitor, Ceramic (MLCC), 0.2pF, ±0.25pF, 50V, ±0.25pF, SMD 0805; Manufacturer: FH(Guangdong Fenghua Advanced Tech); Manufacturer Part Number: 0805CG0R2C500NT
footprint CAP-0805 (0805 (2012M) Capacitor)
pins: 1, 2

## 0805CG0R5B500NT
designator C?  Capacitance: 0.5pF  (hidden comment: *)
Capacitor, Ceramic (MLCC), 0.5pF, ±0.1pF, 50V, C0G, ±0.1pF, SMD 0805; Manufacturer: FH(Guangdong Fenghua Advanced Tech); Manufacturer Part Number: 0805CG0R5B500NT
footprint CAP-0805 (0805 (2012M) Capacitor)
pins: 1, 2

## 0805CG0R5C500NT
designator C?  Capacitance: 0.5pF  (hidden comment: *)
Capacitor, Ceramic (MLCC), 0.5pF, ±0.25pF, 50V, C0G, ±0.25pF, SMD 0805; Manufacturer: FH(Guangdong Fenghua Advanced Tech); Manufacturer Part Number: 0805CG0R5C500NT
footprint CAP-0805 (0805 (2012M) Capacitor)
pins: 1, 2

## 0805CG0R8C500NT
designator C?  Capacitance: 0.8pF  (hidden comment: *)
Capacitor, Ceramic (MLCC), 0.8pF, ±0.25pF, 50V, ±0.25pF, SMD 0805; Manufacturer: FH(Guangdong Fenghua Advanced Tech); Manufacturer Part Number: 0805CG0R8C500NT
footprint CAP-0805 (0805 (2012M) Capacitor)
pins: 1, 2

## 0805CG1R0C500NT
designator C?  Capacitance: 1pF  (hidden comment: *)
Capacitor, Ceramic (MLCC), 1pF, ±0.25pF, 50V, C0G, ±0.25pF, SMD 0805; Manufacturer: FH(Guangdong Fenghua Advanced Tech); Manufacturer Part Number: 0805CG1R0C500NT
footprint CAP-0805 (0805 (2012M) Capacitor)
pins: 1, 2

## 0805CG1R2C500NT
designator C?  Capacitance: 1.2pF  (hidden comment: *)
Capacitor, Ceramic (MLCC), 1.2pF, ±0.25pF, 50V, C0G, ±0.25pF, SMD 0805; Manufacturer: FH(Guangdong Fenghua Advanced Tech); Manufacturer Part Number: 0805CG1R2C500NT
footprint CAP-0805 (0805 (2012M) Capacitor)
pins: 1, 2

## 0805CG1R5C500NT
designator C?  Capacitance: 1.5pF  (hidden comment: *)
Capacitor, Ceramic (MLCC), 1.5pF, ±0.25pF, 50V, C0G, ±0.25pF, SMD 0805; Manufacturer: FH(Guangdong Fenghua Advanced Tech); Manufacturer Part Number: 0805CG1R5C500NT
footprint CAP-0805 (0805 (2012M) Capacitor)
pins: 1, 2

## 0805CG1R8C500NT
designator C?  Capacitance: 1.8pF  (hidden comment: *)
Capacitor, Ceramic (MLCC), 1.8pF, ±0.25pF, 50V, C0G, ±0.25pF, SMD 0805; Manufacturer: FH(Guangdong Fenghua Advanced Tech); Manufacturer Part Number: 0805CG1R8C500NT
footprint CAP-0805 (0805 (2012M) Capacitor)
pins: 1, 2

## 0805CG2R0C500NT
designator C?  Capacitance: 2pF  (hidden comment: *)
Capacitor, Ceramic (MLCC), 2pF, ±0.25pF, 50V, C0G, ±0.25pF, SMD 0805; Manufacturer: FH(Guangdong Fenghua Advanced Tech); Manufacturer Part Number: 0805CG2R0C500NT
footprint CAP-0805 (0805 (2012M) Capacitor)
pins: 1, 2

## 0805CG2R2C500NT
designator C?  Capacitance: 2.2pF  (hidden comment: *)
Capacitor, Ceramic (MLCC), 2.2pF, ±0.25pF, 50V, C0G, ±0.25pF, SMD 0805; Manufacturer: FH(Guangdong Fenghua Advanced Tech); Manufacturer Part Number: 0805CG2R2C500NT
footprint CAP-0805 (0805 (2012M) Capacitor)
pins: 1, 2

## 0805CG2R4C500NT
designator C?  Capacitance: 2.4pF  (hidden comment: *)
Capacitor, Ceramic (MLCC), 2.4pF, ±0.25pF, 50V, C0G, ±0.25pF, SMD 0805; Manufacturer: FH(Guangdong Fenghua Advanced Tech); Manufacturer Part Number: 0805CG2R4C500NT
footprint CAP-0805 (0805 (2012M) Capacitor)
pins: 1, 2

## 0805CG2R5C500NT
designator C?  Capacitance: 2.5pF  (hidden comment: *)
Capacitor, Ceramic (MLCC), 2.5pF, ±0.25pF, 50V, C0G, ±0.25pF, SMD 0805; Manufacturer: FH(Guangdong Fenghua Advanced Tech); Manufacturer Part Number: 0805CG2R5C500NT
footprint CAP-0805 (0805 (2012M) Capacitor)
pins: 1, 2

## 0805CG2R7C500NT
designator C?  Capacitance: 2.7pF  (hidden comment: *)
Capacitor, Ceramic (MLCC), 2.7pF, ±0.25pF, 50V, C0G, ±0.25pF, SMD 0805; Manufacturer: FH(Guangdong Fenghua Advanced Tech); Manufacturer Part Number: 0805CG2R7C500NT
footprint CAP-0805 (0805 (2012M) Capacitor)
pins: 1, 2

## 0805CG3R0C500NT
designator C?  Capacitance: 3pF  (hidden comment: *)
Capacitor, Ceramic (MLCC), 3pF, ±0.25pF, 50V, C0G, ±0.25pF, SMD 0805; Manufacturer: FH(Guangdong Fenghua Advanced Tech); Manufacturer Part Number: 0805CG3R0C500NT
footprint CAP-0805 (0805 (2012M) Capacitor)
pins: 1, 2

## 0805CG3R3C500NT
designator C?  Capacitance: 3.3pF  (hidden comment: *)
Capacitor, Ceramic (MLCC), 3.3pF, ±0.25pF, 50V, C0G, ±0.25pF, SMD 0805; Manufacturer: FH(Guangdong Fenghua Advanced Tech); Manufacturer Part Number: 0805CG3R3C500NT
footprint CAP-0805 (0805 (2012M) Capacitor)
pins: 1, 2

## 0805CG3R6C500NT
designator C?  Capacitance: 3.6pF  (hidden comment: *)
Capacitor, Ceramic (MLCC), 3.6pF, ±0.25pF, 50V, C0G, ±0.25pF, SMD 0805; Manufacturer: FH(Guangdong Fenghua Advanced Tech); Manufacturer Part Number: 0805CG3R6C500NT
footprint CAP-0805 (0805 (2012M) Capacitor)
pins: 1, 2

## 0805CG3R9C500NT
designator C?  Capacitance: 3.9pF  (hidden comment: *)
Capacitor, Ceramic (MLCC), 3.9pF, ±0.25pF, 50V, C0G, ±0.25pF, SMD 0805; Manufacturer: FH(Guangdong Fenghua Advanced Tech); Manufacturer Part Number: 0805CG3R9C500NT
footprint CAP-0805 (0805 (2012M) Capacitor)
pins: 1, 2

## 0805CG4R0B500NT
designator C?  Capacitance: 4pF  (hidden comment: *)
Capacitor, Ceramic (MLCC), 4pF, ±0.1pF, 50V, C0G, ±0.1pF, SMD 0805; Manufacturer: FH(Guangdong Fenghua Advanced Tech); Manufacturer Part Number: 0805CG4R0B500NT
footprint CAP-0805 (0805 (2012M) Capacitor)
pins: 1, 2

## 0805CG4R0C500NT
designator C?  Capacitance: 4pF  (hidden comment: *)
Capacitor, Ceramic (MLCC), 4pF, ±0.25pF, 50V, C0G, ±0.25pF, SMD 0805; Manufacturer: FH(Guangdong Fenghua Advanced Tech); Manufacturer Part Number: 0805CG4R0C500NT
footprint CAP-0805 (0805 (2012M) Capacitor)
pins: 1, 2

## 0805CG4R7C500NT
designator C?  Capacitance: 4.7pF  (hidden comment: *)
Capacitor, Ceramic (MLCC), 4.7pF, ±0.25pF, 50V, C0G, ±0.25pF, SMD 0805; Manufacturer: FH(Guangdong Fenghua Advanced Tech); Manufacturer Part Number: 0805CG4R7C500NT
footprint CAP-0805 (0805 (2012M) Capacitor)
pins: 1, 2

## 0805CG5R0C500NT
designator C?  Capacitance: 5pF  (hidden comment: *)
Capacitor, Ceramic (MLCC), 5pF, ±0.25pF, 50V, C0G, ±0.25pF, SMD 0805; Manufacturer: FH(Guangdong Fenghua Advanced Tech); Manufacturer Part Number: 0805CG5R0C500NT
footprint CAP-0805 (0805 (2012M) Capacitor)
pins: 1, 2

## 0805CG5R1C500NT
designator C?  Capacitance: 5.1pF  (hidden comment: *)
Capacitor, Ceramic (MLCC), 5.1pF, ±0.25pF, 50V, C0G, ±0.25pF, SMD 0805; Manufacturer: FH(Guangdong Fenghua Advanced Tech); Manufacturer Part Number: 0805CG5R1C500NT
footprint CAP-0805 (0805 (2012M) Capacitor)
pins: 1, 2

## 0805CG5R6C500NT
designator C?  Capacitance: 5.6pF  (hidden comment: *)
Capacitor, Ceramic (MLCC), 5.6pF, ±0.25pF, 50V, C0G, ±0.25pF, SMD 0805; Manufacturer: FH(Guangdong Fenghua Advanced Tech); Manufacturer Part Number: 0805CG5R6C500NT
footprint CAP-0805 (0805 (2012M) Capacitor)
pins: 1, 2

## 0805CG6R0C500NT
designator C?  Capacitance: 6pF  (hidden comment: *)
Capacitor, Ceramic (MLCC), 6pF, ±0.25pF, 50V, C0G, ±0.25pF, SMD 0805; Manufacturer: FH(Guangdong Fenghua Advanced Tech); Manufacturer Part Number: 0805CG6R0C500NT
footprint CAP-0805 (0805 (2012M) Capacitor)
pins: 1, 2

## 0805CG6R2C500NT
designator C?  Capacitance: 6.2pF  (hidden comment: *)
Capacitor, Ceramic (MLCC), 6.2pF, ±0.25pF, 50V, C0G, ±0.25pF, SMD 0805; Manufacturer: FH(Guangdong Fenghua Advanced Tech); Manufacturer Part Number: 0805CG6R2C500NT
footprint CAP-0805 (0805 (2012M) Capacitor)
pins: 1, 2

## 0805CG6R8C500NT
designator C?  Capacitance: 6.8pF  (hidden comment: *)
Capacitor, Ceramic (MLCC), 6.8pF, ±0.25pF, 50V, C0G, ±0.25pF, SMD 0805; Manufacturer: FH(Guangdong Fenghua Advanced Tech); Manufacturer Part Number: 0805CG6R8C500NT
footprint CAP-0805 (0805 (2012M) Capacitor)
pins: 1, 2

## 0805CG7R0C500NT
designator C?  Capacitance: 7pF  (hidden comment: *)
Capacitor, Ceramic (MLCC), 7pF, ±0.25pF, 50V, C0G, ±0.25pF, SMD 0805; Manufacturer: FH(Guangdong Fenghua Advanced Tech); Manufacturer Part Number: 0805CG7R0C500NT
footprint CAP-0805 (0805 (2012M) Capacitor)
pins: 1, 2

## 0805CG7R5C500NT
designator C?  Capacitance: 7.5pF  (hidden comment: *)
Capacitor, Ceramic (MLCC), 7.5pF, ±0.25pF, 50V, C0G, ±0.25pF, SMD 0805; Manufacturer: FH(Guangdong Fenghua Advanced Tech); Manufacturer Part Number: 0805CG7R5C500NT
footprint CAP-0805 (0805 (2012M) Capacitor)
pins: 1, 2

## 0805CG8R0C500NT
designator C?  Capacitance: 8pF  (hidden comment: *)
Capacitor, Ceramic (MLCC), 8pF, ±0.25pF, 50V, C0G, ±0.25pF, SMD 0805; Manufacturer: FH(Guangdong Fenghua Advanced Tech); Manufacturer Part Number: 0805CG8R0C500NT
footprint CAP-0805 (0805 (2012M) Capacitor)
pins: 1, 2

## 0805CG8R2C500NT
designator C?  Capacitance: 8.2pF  (hidden comment: *)
Capacitor, Ceramic (MLCC), 8.2pF, ±0.25pF, 50V, C0G, ±0.25pF, SMD 0805; Manufacturer: FH(Guangdong Fenghua Advanced Tech); Manufacturer Part Number: 0805CG8R2C500NT
footprint CAP-0805 (0805 (2012M) Capacitor)
pins: 1, 2

## 0805CG9R0C500NT
designator C?  Capacitance: 9pF  (hidden comment: *)
Capacitor, Ceramic (MLCC), 9pF, ±0.25pF, 50V, C0G, ±0.25pF, SMD 0805; Manufacturer: FH(Guangdong Fenghua Advanced Tech); Manufacturer Part Number: 0805CG9R0C500NT
footprint CAP-0805 (0805 (2012M) Capacitor)
pins: 1, 2

## 0805CG100J101NT
designator C?  Capacitance: 10pF  (hidden comment: *)
Capacitor, Ceramic (MLCC), 10pF, ±5%, 100V, C0G, ±5%, SMD 0805; Manufacturer: FH(Guangdong Fenghua Advanced Tech); Manufacturer Part Number: 0805CG100J101NT
footprint CAP-0805 (0805 (2012M) Capacitor)
pins: 1, 2

## 0805CG100J500NT
designator C?  Capacitance: 10pF  (hidden comment: *)
Capacitor, Ceramic (MLCC), 10pF, ±5%, 50V, C0G, ±5%, SMD 0805; Manufacturer: FH(Guangdong Fenghua Advanced Tech); Manufacturer Part Number: 0805CG100J500NT
footprint CAP-0805 (0805 (2012M) Capacitor)
pins: 1, 2

## 0805CG101F101NT
designator C?  Capacitance: 100pF  (hidden comment: *)
Capacitor, Ceramic (MLCC), 100pF, ±1%, 100V, C0G, ±1%, SMD 0805; Manufacturer: FH(Guangdong Fenghua Advanced Tech); Manufacturer Part Number: 0805CG101F101NT
footprint CAP-0805 (0805 (2012M) Capacitor)
pins: 1, 2

## 0805CG101F500NT
designator C?  Capacitance: 100pF  (hidden comment: *)
Capacitor, Ceramic (MLCC), 100pF, ±1%, 50V, C0G, ±1%, SMD 0805; Manufacturer: FH(Guangdong Fenghua Advanced Tech); Manufacturer Part Number: 0805CG101F500NT
footprint CAP-0805 (0805 (2012M) Capacitor)
pins: 1, 2

## 0805CG101G500NT
designator C?  Capacitance: 100pF  (hidden comment: *)
Capacitor, Ceramic (MLCC), 100pF, ±2%, 50V, C0G, ±2%, SMD 0805; Manufacturer: FH(Guangdong Fenghua Advanced Tech); Manufacturer Part Number: 0805CG101G500NT
footprint CAP-0805 (0805 (2012M) Capacitor)
pins: 1, 2

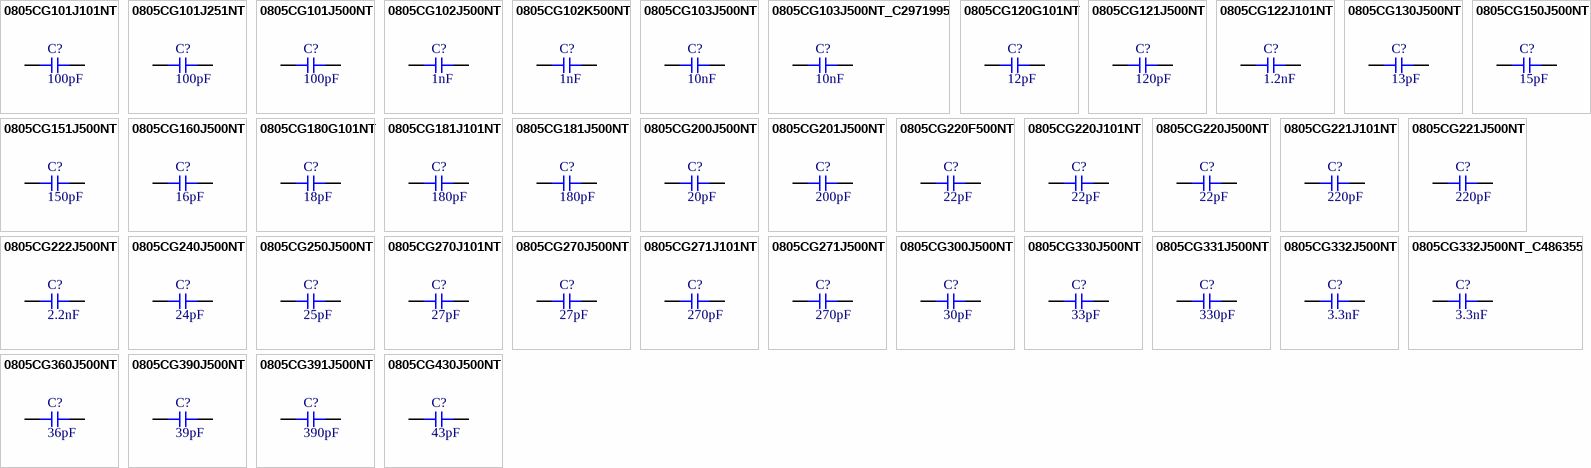
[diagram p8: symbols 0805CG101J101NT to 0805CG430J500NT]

## 0805CG101J101NT
designator C?  Capacitance: 100pF  (hidden comment: *)
Capacitor, Ceramic (MLCC), 100pF, ±5%, 100V, C0G, ±5%, SMD 0805; Manufacturer: FH(Guangdong Fenghua Advanced Tech); Manufacturer Part Number: 0805CG101J101NT
footprint CAP-0805 (0805 (2012M) Capacitor)
pins: 1, 2

## 0805CG101J251NT
designator C?  Capacitance: 100pF  (hidden comment: *)
Capacitor, Ceramic (MLCC), 100pF, ±5%, 250V, C0G, ±5%, SMD 0805; Manufacturer: FH(Guangdong Fenghua Advanced Tech); Manufacturer Part Number: 0805CG101J251NT
footprint CAP-0805 (0805 (2012M) Capacitor)
pins: 1, 2

## 0805CG101J500NT
designator C?  Capacitance: 100pF  (hidden comment: *)
Capacitor, Ceramic (MLCC), 100pF, ±5%, 50V, C0G, ±5%, SMD 0805; Manufacturer: FH(Guangdong Fenghua Advanced Tech); Manufacturer Part Number: 0805CG101J500NT
footprint CAP-0805 (0805 (2012M) Capacitor)
pins: 1, 2

## 0805CG102J500NT
designator C?  Capacitance: 1nF  (hidden comment: *)
Capacitor, Ceramic (MLCC), 1nF, ±5%, 50V, C0G, ±5%, SMD 0805; Manufacturer: FH(Guangdong Fenghua Advanced Tech); Manufacturer Part Number: 0805CG102J500NT
footprint CAP-0805 (0805 (2012M) Capacitor)
pins: 1, 2

## 0805CG102K500NT
designator C?  Capacitance: 1nF  (hidden comment: *)
Capacitor, Ceramic (MLCC), 1nF, ±10%, 50V, C0G, ±10%, SMD 0805; Manufacturer: FH(Guangdong Fenghua Advanced Tech); Manufacturer Part Number: 0805CG102K500NT
footprint CAP-0805 (0805 (2012M) Capacitor)
pins: 1, 2

## 0805CG103J500NT
designator C?  Capacitance: 10nF  (hidden comment: *)
Capacitor, Ceramic (MLCC), 10nF, ±5%, 50V, C0G, ±5%, SMD 0805; Manufacturer: FH(Guangdong Fenghua Advanced Tech); Manufacturer Part Number: 0805CG103J500NT
footprint CAP-0805 (0805 (2012M) Capacitor)
pins: 1, 2

## 0805CG103J500NT_C2971995
designator C?  Capacitance: 10nF  (hidden comment: *)
Capacitor, Ceramic (MLCC), 10nF, ±5%, 50V, C0G, ±5%, SMD 0805; Manufacturer: FH(Guangdong Fenghua Advanced Tech); Manufacturer Part Number: 0805CG103J500NT
footprint CAP-0805 (0805 (2012M) Capacitor)
pins: 1, 2

## 0805CG120G101NT
designator C?  Capacitance: 12pF  (hidden comment: *)
Capacitor, Ceramic (MLCC), 12pF, ±2%, 100V, C0G, ±2%, SMD 0805; Manufacturer: FH(Guangdong Fenghua Advanced Tech); Manufacturer Part Number: 0805CG120G101NT
footprint CAP-0805 (0805 (2012M) Capacitor)
pins: 1, 2

## 0805CG121J500NT
designator C?  Capacitance: 120pF  (hidden comment: *)
Capacitor, Ceramic (MLCC), 120pF, ±5%, 50V, C0G, ±5%, SMD 0805; Manufacturer: FH(Guangdong Fenghua Advanced Tech); Manufacturer Part Number: 0805CG121J500NT
footprint CAP-0805 (0805 (2012M) Capacitor)
pins: 1, 2

## 0805CG122J101NT
designator C?  Capacitance: 1.2nF  (hidden comment: *)
Capacitor, Ceramic (MLCC), 1.2nF, ±5%, 100V, C0G, ±5%, SMD 0805; Manufacturer: FH(Guangdong Fenghua Advanced Tech); Manufacturer Part Number: 0805CG122J101NT
footprint CAP-0805 (0805 (2012M) Capacitor)
pins: 1, 2

## 0805CG130J500NT
designator C?  Capacitance: 13pF  (hidden comment: *)
Capacitor, Ceramic (MLCC), 13pF, ±5%, 50V, C0G, ±5%, SMD 0805; Manufacturer: FH(Guangdong Fenghua Advanced Tech); Manufacturer Part Number: 0805CG130J500NT
footprint CAP-0805 (0805 (2012M) Capacitor)
pins: 1, 2

## 0805CG150J500NT
designator C?  Capacitance: 15pF  (hidden comment: *)
Capacitor, Ceramic (MLCC), 15pF, ±5%, 50V, C0G, ±5%, SMD 0805; Manufacturer: FH(Guangdong Fenghua Advanced Tech); Manufacturer Part Number: 0805CG150J500NT
footprint CAP-0805 (0805 (2012M) Capacitor)
pins: 1, 2

## 0805CG151J500NT
designator C?  Capacitance: 150pF  (hidden comment: *)
Capacitor, Ceramic (MLCC), 150pF, ±5%, 50V, C0G, ±5%, SMD 0805; Manufacturer: FH(Guangdong Fenghua Advanced Tech); Manufacturer Part Number: 0805CG151J500NT
footprint CAP-0805 (0805 (2012M) Capacitor)
pins: 1, 2

## 0805CG160J500NT
designator C?  Capacitance: 16pF  (hidden comment: *)
Capacitor, Ceramic (MLCC), 16pF, ±5%, 50V, C0G, ±5%, SMD 0805; Manufacturer: FH(Guangdong Fenghua Advanced Tech); Manufacturer Part Number: 0805CG160J500NT
footprint CAP-0805 (0805 (2012M) Capacitor)
pins: 1, 2

## 0805CG180G101NT
designator C?  Capacitance: 18pF  (hidden comment: *)
Capacitor, Ceramic (MLCC), 18pF, ±2%, 100V, C0G, ±2%, SMD 0805; Manufacturer: FH(Guangdong Fenghua Advanced Tech); Manufacturer Part Number: 0805CG180G101NT
footprint CAP-0805 (0805 (2012M) Capacitor)
pins: 1, 2

## 0805CG181J101NT
designator C?  Capacitance: 180pF  (hidden comment: *)
Capacitor, Ceramic (MLCC), 180pF, ±5%, 100V, C0G, ±5%, SMD 0805; Manufacturer: FH(Guangdong Fenghua Advanced Tech); Manufacturer Part Number: 0805CG181J101NT
footprint CAP-0805 (0805 (2012M) Capacitor)
pins: 1, 2

## 0805CG181J500NT
designator C?  Capacitance: 180pF  (hidden comment: *)
Capacitor, Ceramic (MLCC), 180pF, ±5%, 50V, C0G, ±5%, SMD 0805; Manufacturer: FH(Guangdong Fenghua Advanced Tech); Manufacturer Part Number: 0805CG181J500NT
footprint CAP-0805 (0805 (2012M) Capacitor)
pins: 1, 2

## 0805CG200J500NT
designator C?  Capacitance: 20pF  (hidden comment: *)
Capacitor, Ceramic (MLCC), 20pF, ±5%, 50V, C0G, ±5%, SMD 0805; Manufacturer: FH(Guangdong Fenghua Advanced Tech); Manufacturer Part Number: 0805CG200J500NT
footprint CAP-0805 (0805 (2012M) Capacitor)
pins: 1, 2

## 0805CG201J500NT
designator C?  Capacitance: 200pF  (hidden comment: *)
Capacitor, Ceramic (MLCC), 200pF, ±5%, 50V, C0G, ±5%, SMD 0805; Manufacturer: FH(Guangdong Fenghua Advanced Tech); Manufacturer Part Number: 0805CG201J500NT
footprint CAP-0805 (0805 (2012M) Capacitor)
pins: 1, 2

## 0805CG220F500NT
designator C?  Capacitance: 22pF  (hidden comment: *)
Capacitor, Ceramic (MLCC), 22pF, ±1%, 50V, C0G, ±1%, SMD 0805; Manufacturer: FH(Guangdong Fenghua Advanced Tech); Manufacturer Part Number: 0805CG220F500NT
footprint CAP-0805 (0805 (2012M) Capacitor)
pins: 1, 2

## 0805CG220J101NT
designator C?  Capacitance: 22pF  (hidden comment: *)
Capacitor, Ceramic (MLCC), 22pF, ±5%, 100V, C0G, ±5%, SMD 0805; Manufacturer: FH(Guangdong Fenghua Advanced Tech); Manufacturer Part Number: 0805CG220J101NT
footprint CAP-0805 (0805 (2012M) Capacitor)
pins: 1, 2

## 0805CG220J500NT
designator C?  Capacitance: 22pF  (hidden comment: *)
Capacitor, Ceramic (MLCC), 22pF, ±5%, 50V, C0G, ±5%, SMD 0805; Manufacturer: FH(Guangdong Fenghua Advanced Tech); Manufacturer Part Number: 0805CG220J500NT
footprint CAP-0805 (0805 (2012M) Capacitor)
pins: 1, 2

## 0805CG221J101NT
designator C?  Capacitance: 220pF  (hidden comment: *)
Capacitor, Ceramic (MLCC), 220pF, ±5%, 100V, C0G, ±5%, SMD 0805; Manufacturer: FH(Guangdong Fenghua Advanced Tech); Manufacturer Part Number: 0805CG221J101NT
footprint CAP-0805 (0805 (2012M) Capacitor)
pins: 1, 2

## 0805CG221J500NT
designator C?  Capacitance: 220pF  (hidden comment: *)
Capacitor, Ceramic (MLCC), 220pF, ±5%, 50V, C0G, ±5%, SMD 0805; Manufacturer: FH(Guangdong Fenghua Advanced Tech); Manufacturer Part Number: 0805CG221J500NT
footprint CAP-0805 (0805 (2012M) Capacitor)
pins: 1, 2

## 0805CG222J500NT
designator C?  Capacitance: 2.2nF  (hidden comment: *)
Capacitor, Ceramic (MLCC), 2.2nF, ±5%, 50V, C0G, ±5%, SMD 0805; Manufacturer: FH(Guangdong Fenghua Advanced Tech); Manufacturer Part Number: 0805CG222J500NT
footprint CAP-0805 (0805 (2012M) Capacitor)
pins: 1, 2

## 0805CG240J500NT
designator C?  Capacitance: 24pF  (hidden comment: *)
Capacitor, Ceramic (MLCC), 24pF, ±5%, 50V, C0G, ±5%, SMD 0805; Manufacturer: FH(Guangdong Fenghua Advanced Tech); Manufacturer Part Number: 0805CG240J500NT
footprint CAP-0805 (0805 (2012M) Capacitor)
pins: 1, 2

## 0805CG250J500NT
designator C?  Capacitance: 25pF  (hidden comment: *)
Capacitor, Ceramic (MLCC), 25pF, ±5%, 50V, C0G, ±5%, SMD 0805; Manufacturer: FH(Guangdong Fenghua Advanced Tech); Manufacturer Part Number: 0805CG250J500NT
footprint CAP-0805 (0805 (2012M) Capacitor)
pins: 1, 2

## 0805CG270J101NT
designator C?  Capacitance: 27pF  (hidden comment: *)
Capacitor, Ceramic (MLCC), 27pF, ±5%, 100V, C0G, ±5%, SMD 0805; Manufacturer: FH(Guangdong Fenghua Advanced Tech); Manufacturer Part Number: 0805CG270J101NT
footprint CAP-0805 (0805 (2012M) Capacitor)
pins: 1, 2

## 0805CG270J500NT
designator C?  Capacitance: 27pF  (hidden comment: *)
Capacitor, Ceramic (MLCC), 27pF, ±5%, 50V, C0G, ±5%, SMD 0805; Manufacturer: FH(Guangdong Fenghua Advanced Tech); Manufacturer Part Number: 0805CG270J500NT
footprint CAP-0805 (0805 (2012M) Capacitor)
pins: 1, 2

## 0805CG271J101NT
designator C?  Capacitance: 270pF  (hidden comment: *)
Capacitor, Ceramic (MLCC), 270pF, ±5%, 100V, C0G, ±5%, SMD 0805; Manufacturer: FH(Guangdong Fenghua Advanced Tech); Manufacturer Part Number: 0805CG271J101NT
footprint CAP-0805 (0805 (2012M) Capacitor)
pins: 1, 2

## 0805CG271J500NT
designator C?  Capacitance: 270pF  (hidden comment: *)
Capacitor, Ceramic (MLCC), 270pF, ±5%, 50V, C0G, ±5%, SMD 0805; Manufacturer: FH(Guangdong Fenghua Advanced Tech); Manufacturer Part Number: 0805CG271J500NT
footprint CAP-0805 (0805 (2012M) Capacitor)
pins: 1, 2

## 0805CG300J500NT
designator C?  Capacitance: 30pF  (hidden comment: *)
Capacitor, Ceramic (MLCC), 30pF, ±5%, 50V, C0G, ±5%, SMD 0805; Manufacturer: FH(Guangdong Fenghua Advanced Tech); Manufacturer Part Number: 0805CG300J500NT
footprint CAP-0805 (0805 (2012M) Capacitor)
pins: 1, 2

## 0805CG330J500NT
designator C?  Capacitance: 33pF  (hidden comment: *)
Capacitor, Ceramic (MLCC), 33pF, ±5%, 50V, C0G, ±5%, SMD 0805; Manufacturer: FH(Guangdong Fenghua Advanced Tech); Manufacturer Part Number: 0805CG330J500NT
footprint CAP-0805 (0805 (2012M) Capacitor)
pins: 1, 2

## 0805CG331J500NT
designator C?  Capacitance: 330pF  (hidden comment: *)
Capacitor, Ceramic (MLCC), 330pF, ±5%, 50V, C0G, ±5%, SMD 0805; Manufacturer: FH(Guangdong Fenghua Advanced Tech); Manufacturer Part Number: 0805CG331J500NT
footprint CAP-0805 (0805 (2012M) Capacitor)
pins: 1, 2

## 0805CG332J500NT
designator C?  Capacitance: 3.3nF  (hidden comment: *)
Capacitor, Ceramic (MLCC), 3.3nF, ±5%, 50V, C0G, ±5%, SMD 0805; Manufacturer: FH(Guangdong Fenghua Advanced Tech); Manufacturer Part Number: 0805CG332J500NT
footprint CAP-0805 (0805 (2012M) Capacitor)
pins: 1, 2

## 0805CG332J500NT_C486355
designator C?  Capacitance: 3.3nF  (hidden comment: *)
Capacitor, Ceramic (MLCC), 3.3nF, ±5%, 50V, C0G, ±5%, SMD 0805; Manufacturer: FH(Guangdong Fenghua Advanced Tech); Manufacturer Part Number: 0805CG332J500NT
footprint CAP-0805 (0805 (2012M) Capacitor)
pins: 1, 2

## 0805CG360J500NT
designator C?  Capacitance: 36pF  (hidden comment: *)
Capacitor, Ceramic (MLCC), 36pF, ±5%, 50V, C0G, ±5%, SMD 0805; Manufacturer: FH(Guangdong Fenghua Advanced Tech); Manufacturer Part Number: 0805CG360J500NT
footprint CAP-0805 (0805 (2012M) Capacitor)
pins: 1, 2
